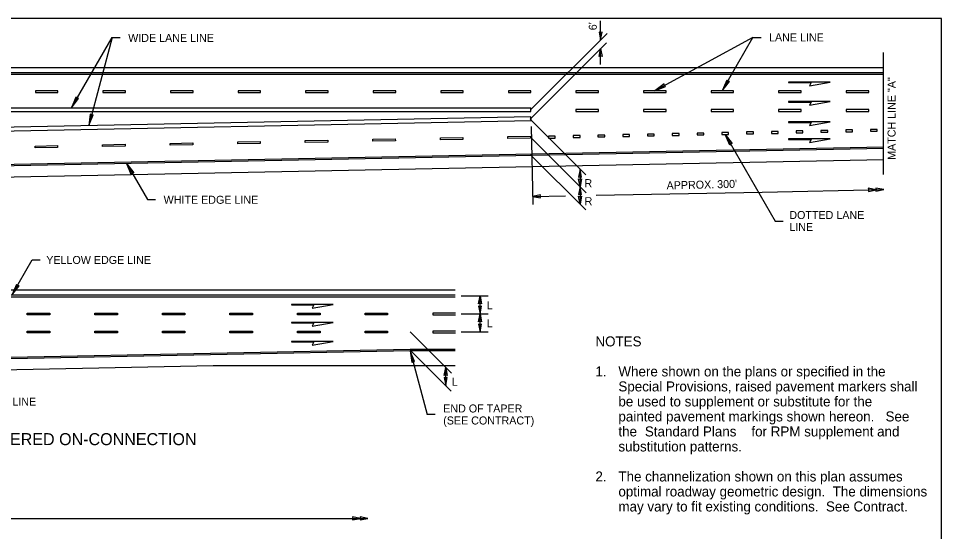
# Model space of a CAD drawing. Extents: x 99862 to 103151, y 100339 to 102415.
# Drawn here: x 101307 to 103151, y 101389 to 102415 of the extents above; entities that cross this region are included whole.
import ezdxf

# ---------------------------------------------------------------- set-up
doc = ezdxf.new("R2010")
doc.units = 0
for name, color, linetype in [('Level 1', 7, 'Continuous'), ('Level 15', 7, 'Continuous'), ('Level 2', 7, 'Continuous'), ('Level 20', 7, 'Continuous'), ('Level 3', 7, 'Continuous'), ('Level 4', 7, 'Continuous'), ('Level 5', 7, 'Continuous'), ('Level 6', 7, 'Continuous'), ('Level 60', 7, 'Continuous')]:
    doc.layers.add(name, color=color, linetype=linetype)

msp = doc.modelspace()

# ---------------------------------------------------------------- linework, layer by layer
at = {"layer": 'Level 1'}
msp.add_lwpolyline([(99862, 100338.8), (103151, 100338.8), (103151, 102414.8), (99862, 102414.8)], close=True, dxfattribs=at)
at = {"layer": 'Level 15'}
for p, q in [((102469.9, 102371.8), (102469.9, 102409.7)), ((101412.8, 102236.2), (101494, 102376.9)), ((101494, 102376.9), (101447.1, 102200.6)), ((101494, 102376.9), (101510, 102376.9)), ((102330.7, 102232.5), (102483.1, 102385)), ((102774.3, 102376.5), (102578, 102270.4)), ((102713, 102270.4), (102774.3, 102376.5)), ((102774.3, 102376.5), (102790.3, 102376.5)), ((102328.8, 102213.3), (102481.3, 102365.8)), ((102469.9, 102322.5), (102469.9, 102354.5)), ((102440.1, 102102), (102328.8, 102213.3)), ((102331, 102198.7), (102334.2, 102042.7)), ((102441.1, 102066.2), (102329.7, 102177.6)), ((102718.8, 102183), (102818.9, 102009.8)), ((102440.1, 102032), (102330.1, 102142.1)), ((101523.1, 102124.3), (101564.5, 102052.6)), ((102428.8, 102113.3), (102428.8, 102078.5)), ((102428.8, 102078.5), (102428.8, 102043.4)), ((101564.5, 102052.6), (101580.8, 102052.6)), ((102818.9, 102009.8), (102834.9, 102009.8)), ((101293.8, 101861.8), (101334.3, 101932)), ((101334.3, 101932), (101350.3, 101932)), ((102191.1, 101860), (102245.1, 101860)), ((102229.1, 101824), (102229.1, 101859.7)), ((102191.1, 101824), (102245.1, 101824)), ((102229.1, 101788), (102229.1, 101824)), ((102171.7, 101705.6), (102089.3, 101788)), ((102191.1, 101788), (102245.1, 101788)), ((102171.6, 101669.7), (102089.3, 101751.9)), ((102089.3, 101750.1), (102123.4, 101623.1)), ((102160.4, 101680.9), (102160.4, 101716.9)), ((102139.4, 101623.1), (102123.4, 101623.1)), ((100203.5, 101415.4), (102005, 101415.4))]:
    msp.add_line(p, q, dxfattribs=at)
for points in [[(102469.9, 102371.8), (102473, 102387.6), (102469.9, 102386.9), (102466.8, 102387.6)], [(102469.9, 102354.5), (102473, 102338.7), (102469.9, 102339.4), (102466.8, 102338.7)], [(102578, 102270.4), (102599.7, 102278.6), (102597.3, 102280.8), (102596.8, 102283.9)], [(102713, 102270.4), (102727.1, 102288.7), (102724, 102289.3), (102721.9, 102291.7)], [(101412.8, 102236.2), (101426.9, 102254.6), (101423.8, 102255.2), (101421.7, 102257.6)], [(101447.1, 102200.6), (101455.9, 102222), (101452.7, 102221.7), (101450.1, 102223.5)], [(102718.8, 102183), (102732.9, 102164.7), (102729.8, 102164.1), (102727.7, 102161.7)], [(101523.1, 102124.3), (101537.2, 102105.9), (101534.1, 102105.3), (101532, 102102.9)], [(102428.8, 102113.3), (102425.7, 102097.5), (102428.8, 102098.2), (102431.9, 102097.5)], [(102428.8, 102078.5), (102425.7, 102094.3), (102428.8, 102093.5), (102431.9, 102094.3)], [(102333.8, 102058.7), (102349.7, 102055.9), (102348.9, 102058.9), (102349.6, 102062.1)], [(102428.8, 102078.5), (102425.7, 102062.7), (102428.8, 102063.4), (102431.9, 102062.7)], [(103020.5, 102072.4), (103004.7, 102075.2), (103005.5, 102072.1), (103004.8, 102069)], [(103035.6, 102072.7), (103019.7, 102075.5), (103020.5, 102072.4), (103019.9, 102069.3)], [(102428.8, 102043.4), (102425.7, 102059.2), (102428.8, 102058.4), (102431.9, 102059.2)], [(101293.8, 101861.8), (101307.9, 101880.2), (101304.8, 101880.8), (101302.7, 101883.2)], [(102229.1, 101860), (102232.2, 101844.2), (102229.1, 101844.9), (102226, 101844.2)], [(102229.1, 101824), (102232.2, 101839.8), (102229.1, 101839), (102226, 101839.8)], [(102229.1, 101824), (102232.2, 101808.2), (102229.1, 101808.9), (102226, 101808.2)], [(102229.1, 101788), (102232.2, 101803.8), (102229.1, 101803), (102226, 101803.8)], [(102089.3, 101750.1), (102092.4, 101727.3), (102095, 101729), (102098.1, 101728.8)], [(102160.4, 101716.9), (102163.5, 101701.1), (102160.4, 101701.9), (102157.3, 101701.1)], [(102160.4, 101680.9), (102163.5, 101696.7), (102160.4, 101696), (102157.3, 101696.7)], [(101989.9, 101415.4), (101974.1, 101418.5), (101974.8, 101415.4), (101974.1, 101412.3)], [(102005, 101415.4), (101989.2, 101418.5), (101989.9, 101415.4), (101989.2, 101412.3)]]:
    msp.add_lwpolyline(points, close=True, dxfattribs=at)
for points in [[(102461.1, 102061.2), (102792.3, 102067.8)], [(102792.3, 102067.8), (103035.6, 102072.7)], [(102333.8, 102058.7), (102400, 102060)]]:
    msp.add_lwpolyline(points, dxfattribs=at)
at = {"layer": 'Level 2'}
for p, q in [((99957.8, 102316.5), (103035.2, 102316.5)), ((101130.9, 102094.5), (103035.2, 102132.6)), ((100094.2, 101872), (102179.3, 101872))]:
    msp.add_line(p, q, dxfattribs=at)
msp.add_lwpolyline([(102179.3, 101720.1), (101695.8, 101720.1), (100094.2, 101688)], dxfattribs=at)
at = {"layer": 'Level 3'}
for p, q in [((99957.8, 102306.4), (103035.2, 102306.4)), ((103035.2, 102302.6), (99957.8, 102302.6)), ((100473.5, 102236.2), (102330.7, 102236.2)), ((100473.5, 102228.7), (102330.7, 102228.7)), ((102330.7, 102228.7), (102330.7, 102236.2)), ((101130.9, 102120.4), (103035.2, 102158.4)), ((103035.2, 102154.7), (101130.9, 102116.6)), ((102179.3, 101861.8), (100094.2, 101861.8)), ((100094.2, 101858.1), (102179.3, 101858.1))]:
    msp.add_line(p, q, dxfattribs=at)
for points in [[(101131, 102186.7), (102330.8, 102210.7), (102330.7, 102218.2), (101130.8, 102194.2)], [(100094.2, 101713.9), (102089.3, 101753.8), (102179.3, 101753.8)], [(102179.3, 101750.1), (102089.3, 101750.1), (100094.2, 101710.2)]]:
    msp.add_lwpolyline(points, dxfattribs=at)
at = {"layer": 'Level 4'}
msp.add_line((102180, 101789.8), (102134.6, 101789.8), dxfattribs=at)
for points in [[(101385.5, 102270.4), (101340.5, 102270.4), (101340.5, 102266.6), (101385.5, 102266.6)], [(101520.5, 102270.4), (101475.5, 102270.4), (101475.5, 102266.6), (101520.5, 102266.6)], [(101655.5, 102270.4), (101610.5, 102270.4), (101610.5, 102266.6), (101655.5, 102266.6)], [(101790.5, 102270.4), (101745.5, 102270.4), (101745.5, 102266.6), (101790.5, 102266.6)], [(101925.5, 102270.4), (101880.5, 102270.4), (101880.5, 102266.6), (101925.5, 102266.6)], [(102060.5, 102270.4), (102015.5, 102270.4), (102015.5, 102266.6), (102060.5, 102266.6)], [(102195.5, 102270.4), (102150.5, 102270.4), (102150.5, 102266.6), (102195.5, 102266.6)], [(102330.5, 102270.4), (102285.5, 102270.4), (102285.5, 102266.6), (102330.5, 102266.6)], [(102465.5, 102270.4), (102420.5, 102270.4), (102420.5, 102266.6), (102465.5, 102266.6)], [(102600.5, 102270.4), (102555.5, 102270.4), (102555.5, 102266.6), (102600.5, 102266.6)], [(102735.5, 102270.4), (102690.5, 102270.4), (102690.5, 102266.6), (102735.5, 102266.6)], [(102870.5, 102270.4), (102825.5, 102270.4), (102825.5, 102266.6), (102870.5, 102266.6)], [(103005.5, 102270.4), (102960.5, 102270.4), (102960.5, 102266.6), (103005.5, 102266.6)], [(102465.5, 102232.5), (102420.5, 102232.5), (102420.5, 102228.7), (102465.5, 102228.7)], [(102600.5, 102232.5), (102555.5, 102232.5), (102555.5, 102228.7), (102600.5, 102228.7)], [(102735.5, 102232.5), (102690.5, 102232.5), (102690.5, 102228.7), (102735.5, 102228.7)], [(102870.5, 102232.5), (102825.5, 102232.5), (102825.5, 102228.7), (102870.5, 102228.7)], [(103005.5, 102232.5), (102960.5, 102232.5), (102960.5, 102228.7), (103005.5, 102228.7)], [(102910, 102187.2), (102923.5, 102187.2), (102923.5, 102191), (102910, 102191)], [(102959.5, 102188.3), (102973, 102188.3), (102973, 102192), (102959.5, 102192)], [(103009, 102189.3), (103022.5, 102189.3), (103022.5, 102193.1), (103009, 102193.1)], [(102014.7, 102173.2), (102059.7, 102174.1), (102059.8, 102170.3), (102014.8, 102169.4)], [(102149.7, 102175.9), (102194.7, 102176.8), (102194.8, 102173), (102149.8, 102172.1)], [(102284.7, 102178.6), (102329.7, 102179.5), (102329.7, 102175.7), (102284.8, 102174.8)], [(102365.7, 102175.7), (102379.2, 102175.7), (102379.2, 102179.5), (102365.7, 102179.5)], [(102415.2, 102176.8), (102428.7, 102176.8), (102428.7, 102180.5), (102415.2, 102180.5)], [(102464.6, 102177.8), (102478.1, 102177.8), (102478.1, 102181.6), (102464.6, 102181.6)], [(102514.1, 102178.8), (102527.6, 102178.8), (102527.6, 102182.6), (102514.1, 102182.6)], [(102563.6, 102179.9), (102577.1, 102179.9), (102577.1, 102183.6), (102563.6, 102183.6)], [(102613.1, 102180.9), (102626.6, 102180.9), (102626.6, 102184.7), (102613.1, 102184.7)], [(102662.6, 102182), (102676.1, 102182), (102676.1, 102185.7), (102662.6, 102185.7)], [(102712.1, 102183), (102725.6, 102183), (102725.6, 102186.8), (102712.1, 102186.8)], [(102761.6, 102184.1), (102775.1, 102184.1), (102775.1, 102187.8), (102761.6, 102187.8)], [(102811.1, 102185.1), (102824.6, 102185.1), (102824.6, 102188.9), (102811.1, 102188.9)], [(102860.6, 102186.2), (102874.1, 102186.2), (102874.1, 102189.9), (102860.6, 102189.9)], [(101339.9, 102159.7), (101384.9, 102160.6), (101384.9, 102156.8), (101339.9, 102155.9)], [(101474.8, 102162.4), (101519.8, 102163.3), (101519.9, 102159.5), (101474.9, 102158.6)], [(101609.8, 102165.1), (101654.8, 102166), (101654.9, 102162.2), (101609.9, 102161.3)], [(101744.8, 102167.8), (101789.8, 102168.7), (101789.9, 102164.9), (101744.9, 102164)], [(101879.8, 102170.5), (101924.8, 102171.4), (101924.8, 102167.6), (101879.8, 102166.7)], [(101324.3, 101825.8), (101369.3, 101825.8), (101369.3, 101822.1), (101324.3, 101822.1)], [(101459.3, 101825.8), (101504.3, 101825.8), (101504.3, 101822.1), (101459.3, 101822.1)], [(101594.3, 101825.8), (101639.3, 101825.8), (101639.3, 101822.1), (101594.3, 101822.1)], [(101729.3, 101825.8), (101774.3, 101825.8), (101774.3, 101822.1), (101729.3, 101822.1)], [(101864.3, 101825.8), (101909.3, 101825.8), (101909.3, 101822.1), (101864.3, 101822.1)], [(101999.3, 101825.8), (102044.3, 101825.8), (102044.3, 101822.1), (101999.3, 101822.1)], [(101324.3, 101789.8), (101369.3, 101789.8), (101369.3, 101786.1), (101324.3, 101786.1)], [(101459.3, 101789.8), (101504.3, 101789.8), (101504.3, 101786.1), (101459.3, 101786.1)], [(101594.3, 101789.8), (101639.3, 101789.8), (101639.3, 101786.1), (101594.3, 101786.1)], [(101729.3, 101789.8), (101774.3, 101789.8), (101774.3, 101786.1), (101729.3, 101786.1)], [(101864.3, 101789.8), (101909.3, 101789.8), (101909.3, 101786.1), (101864.3, 101786.1)], [(101999.3, 101789.8), (102044.3, 101789.8), (102044.3, 101786.1), (101999.3, 101786.1)]]:
    msp.add_lwpolyline(points, close=True, dxfattribs=at)
for points in [[(102180, 101825.8), (102134.6, 101825.8), (102134.6, 101822.1), (102180, 101822.1)], [(102134.6, 101789.8), (102134.6, 101786.1), (102180, 101786.1)]]:
    msp.add_lwpolyline(points, dxfattribs=at)
at = {"layer": 'Level 5'}
for points in [[(102845.4, 102286.5), (102890.5, 102286.5), (102887, 102280.3), (102928.5, 102287.7), (102845.4, 102287.7)], [(102845.4, 102247.7), (102890.5, 102247.7), (102887, 102241.6), (102928.5, 102248.9), (102845.4, 102248.9)], [(102845.4, 102207), (102890.5, 102207), (102887, 102200.9), (102928.5, 102208.2), (102845.4, 102208.2)], [(102845.4, 102173), (102890.5, 102173), (102887, 102166.9), (102928.5, 102174.2), (102845.4, 102174.2)], [(101852.1, 101842), (101897.2, 101842), (101893.6, 101835.8), (101935.2, 101843.1), (101852.1, 101843.1)], [(101852.1, 101806), (101897.2, 101806), (101893.6, 101799.8), (101935.2, 101807.1), (101852.1, 101807.1)], [(101852.1, 101768), (101897.2, 101768), (101893.6, 101761.9), (101935.2, 101769.2), (101852.1, 101769.2)]]:
    msp.add_lwpolyline(points, close=True, dxfattribs=at)
at = {"layer": 'Level 6'}
msp.add_line((103035.2, 102102.6), (103035.2, 102346.5), dxfattribs=at)
at = {"layer": 'Level 60'}
msp.add_line((103151, 102414.8), (103151, 102414.8), dxfattribs=at)

# ---------------------------------------------------------------- texts
at = {"layer": 'Level 20'}
for s, rotation, p in [("6'", 90, (102462.2, 102391.2)), ('MATCH LINE "A"', 90, (103059.2, 102132.2)), (" APPROX. 300'", 1.3639, (102595.9, 102072.8))]:
    msp.add_text(s, height=16, rotation=rotation, dxfattribs=at).set_placement(p)
for s, height, p in [('WIDE LANE LINE', 16, (101526, 102367.9)), ('LANE LINE', 16, (102806.3, 102368.9)), ('R', 16, (102437.5, 102077.5)), ('WHITE EDGE LINE', 16, (101596.8, 102044.3)), ('R', 16, (102437.9, 102041.5)), ('DOTTED LANE', 16, (102846.9, 102013.8)), ('LINE', 16, (102846.9, 101989.8)), ('YELLOW EDGE LINE', 16, (101362.3, 101924)), ('L', 16, (102242.3, 101833.3)), ('L', 16, (102242.4, 101797.5)), ('NOTES', 20, (102459.5, 101759.2)), ('1.', 20, (102459.5, 101699.2)), ('Where shown on the plans or specified in the ', 20, (102505.4, 101699.2)), ('L', 16, (102172.5, 101680.5)), ('Special Provisions, raised pavement markers shall ', 20, (102505.4, 101669.2)), ('WHITE EDGE LINE', 16, (101153.1, 101640.7)), ('be used to supplement or substitute for the ', 20, (102505.4, 101639.2)), ('END OF TAPER', 16, (102155.4, 101627.1)), ('(SEE CONTRACT)', 16, (102155.4, 101603.1)), ('painted pavement markings shown hereon.   See ', 20, (102505.4, 101609.2)), ('the ', 20, (102505.4, 101579.2)), ('Standard Plans ', 20, (102558.3, 101579.2)), ('for RPM supplement and ', 20, (102771.1, 101579.2)), ('TWO-LANE TAPERED ON-CONNECTION', 24, (101049.1, 101561.8)), ('substitution patterns.', 20, (102505.4, 101549.2)), ('2.', 20, (102459.5, 101489.2)), ('The channelization shown on this plan assumes ', 20, (102505.4, 101489.2)), ('optimal roadway geometric design.  The dimensions ', 20, (102505.4, 101459.2)), ('may vary to fit existing conditions.  See Contract.', 20, (102505.4, 101429.2))]:
    msp.add_text(s, height=height, dxfattribs=at).set_placement(p)

doc.saveas('drawing.dxf')
